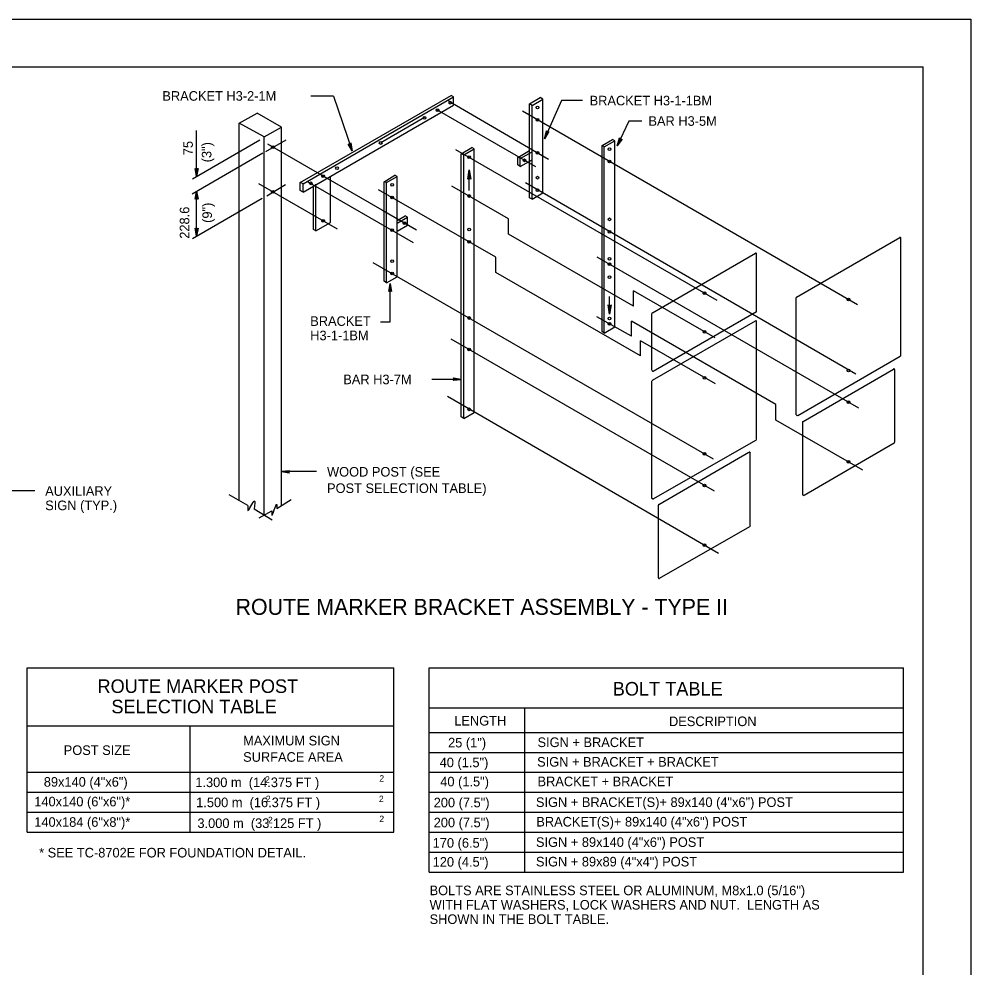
# Model space of a CAD drawing. Extents: x 649454 to 651200, y 295188 to 295782.
# Drawn here: x 650838.3 to 651136.3, y 295484.6 to 295781.6 of the extents above; entities that cross this region are included whole.
import ezdxf

# ---------------------------------------------------------------- set-up
doc = ezdxf.new("R2010")
doc.units = 0
for name, color, linetype in [('1', 7, 'Continuous'), ('2', 7, 'Continuous'), ('3', 7, 'Continuous'), ('PLT-BNDY', 7, 'Continuous')]:
    doc.layers.add(name, color=color, linetype=linetype)

msp = doc.modelspace()

# ---------------------------------------------------------------- linework, layer by layer
at = {"layer": '1'}
for p in [(650335.31, 295766.63), (651121.31, 295202.63)]:
    msp.add_line(p, (651121.31, 295766.63), dxfattribs=at)
at = {"layer": '2'}
for p, q in [((650840.87, 295578.52), (650955.61, 295578.52)), ((650840.87, 295527.15), (650840.87, 295578.52)), ((650955.61, 295527.15), (650955.61, 295578.52)), ((650966.73, 295578.52), (651115.19, 295578.52)), ((650966.73, 295514.65), (650966.73, 295578.52)), ((651115.19, 295514.65), (651115.19, 295578.52)), ((650966.73, 295566.02), (651115.19, 295566.02)), ((650996.61, 295514.65), (650996.61, 295565.9)), ((650840.87, 295560.46), (650955.61, 295560.46)), ((650891.86, 295527.02), (650891.86, 295560.34)), ((650966.73, 295558.27), (651115.19, 295558.27)), ((650966.73, 295552.02), (651115.19, 295552.02)), ((650840.87, 295545.9), (650955.61, 295545.9)), ((650966.73, 295545.9), (651115.19, 295545.9)), ((650840.87, 295539.65), (650955.61, 295539.65)), ((650966.73, 295539.65), (651115.19, 295539.65)), ((650840.87, 295533.4), (650955.61, 295533.4)), ((650966.73, 295533.4), (651115.19, 295533.4)), ((650840.87, 295527.15), (650955.61, 295527.15)), ((650966.73, 295527.15), (651115.19, 295527.15)), ((650966.73, 295520.9), (651115.19, 295520.9)), ((650966.73, 295514.65), (651115.19, 295514.65))]:
    msp.add_line(p, q, dxfattribs=at)
for points in [[(650936.7, 295757.45), (650929.62, 295757.45)], [(650936.7, 295757.45), (650942.56, 295740.33)], [(651008.11, 295756.11), (651002.79, 295744.14)], [(651014.71, 295756.11), (651008.11, 295756.11)], [(651033.31, 295749.71), (651029.19, 295749.71), (651025.56, 295741.96)], [(651004.04, 295746.27), (651003.79, 295746.27), (651002.79, 295744.14), (651004.04, 295746.27), (651004.16, 295746.39), (651002.79, 295744.14), (651003.54, 295746.39), (651003.54, 295746.52), (651002.79, 295744.14), (651003.41, 295746.64), (651003.54, 295746.52)], [(651026.94, 295743.96), (651026.69, 295743.96), (651025.56, 295741.96), (651026.94, 295743.96), (651027.06, 295744.08), (651025.56, 295741.96), (651026.44, 295744.08), (651026.31, 295744.21), (651025.56, 295741.96), (651026.31, 295744.46), (651026.31, 295744.21)], [(650942.06, 295742.58), (650941.94, 295742.46), (650942.56, 295740.33), (650942.06, 295742.58), (650942.19, 295742.83), (650942.56, 295740.33), (650941.69, 295742.46), (650941.56, 295742.46), (650942.56, 295740.33), (650941.31, 295742.46), (650941.56, 295742.46)], [(650951.44, 295686.83), (650954.44, 295686.83), (650954.44, 295698.83)], [(650954.19, 295696.46), (650954.31, 295696.58), (650954.44, 295698.83), (650954.19, 295696.46), (650954.06, 295696.33), (650954.44, 295698.83), (650954.56, 295696.58), (650954.81, 295696.46), (650954.44, 295698.83), (650954.94, 295696.33), (650954.81, 295696.46)], [(650976.69, 295668.83), (650967.56, 295668.83)], [(650974.31, 295669.21), (650974.44, 295668.96), (650976.69, 295668.83), (650974.31, 295669.21), (650974.19, 295669.21), (650976.69, 295668.83), (650974.44, 295668.71), (650974.31, 295668.58), (650976.69, 295668.83), (650974.19, 295668.46), (650974.31, 295668.58)], [(650922.81, 295639.58), (650922.69, 295639.83), (650920.44, 295639.96), (650922.81, 295639.58), (650922.94, 295639.46), (650920.44, 295639.96), (650922.69, 295640.08), (650922.81, 295640.21), (650920.44, 295639.96), (650922.94, 295640.33), (650922.81, 295640.21)], [(650931.38, 295639.96), (650920.44, 295639.96)], [(650843.26, 295633.97), (650833.19, 295633.97)]]:
    msp.add_lwpolyline(points, dxfattribs=at)
at = {"layer": '3'}
for p, q in [((650926.31, 295730.46), (650973.56, 295757.71)), ((650927.19, 295730.08), (650974.31, 295757.33)), ((651004.06, 295737.71), (650972.69, 295755.96)), ((650972.81, 295757.46), (650972.81, 295757.46)), ((650974.31, 295757.33), (650973.56, 295757.71)), ((650974.31, 295754.71), (650974.31, 295757.33)), ((650998.06, 295755.08), (651001.44, 295757.08)), ((650998.94, 295754.58), (651002.31, 295756.58)), ((651002.31, 295756.58), (651001.44, 295757.08)), ((651002.31, 295727.21), (651002.31, 295756.58)), ((650907.19, 295749.08), (650912.81, 295752.21)), ((650920.44, 295747.83), (650912.81, 295752.21)), ((650927.19, 295727.46), (650974.31, 295754.71)), ((651000.06, 295735.33), (650969.31, 295753.08)), ((650973.69, 295754.46), (650973.69, 295754.46)), ((651100.81, 295692.21), (650995.94, 295752.83)), ((650998.06, 295725.71), (650998.06, 295755.08)), ((650998.94, 295754.58), (650998.06, 295755.08)), ((650998.94, 295725.21), (650998.94, 295754.58)), ((650965.19, 295750.83), (650951.56, 295742.83)), ((650893.81, 295732.46), (650893.81, 295746.78)), ((650907.19, 295630.83), (650907.19, 295749.08)), ((650915.06, 295744.71), (650907.19, 295749.08)), ((650915.06, 295744.71), (650920.44, 295747.83)), ((650920.44, 295629.46), (650920.44, 295747.83)), ((650892.56, 295731.58), (650913.69, 295743.83)), ((650915.06, 295626.21), (650915.06, 295744.71)), ((650915.56, 295740.21), (650921.94, 295743.83)), ((651020.81, 295742.08), (651024.06, 295743.96)), ((651021.44, 295741.58), (651024.81, 295743.46)), ((651024.81, 295743.46), (651024.06, 295743.96)), ((651024.81, 295685.33), (651024.81, 295743.46)), ((650960.81, 295716.71), (650916.19, 295742.46)), ((650917.81, 295741.58), (650917.81, 295741.58)), ((651056.81, 295693.58), (650975.06, 295740.71)), ((650976.69, 295739.46), (650980.06, 295741.46)), ((650977.56, 295739.08), (650980.81, 295740.96)), ((650980.81, 295740.96), (650980.06, 295741.46)), ((650980.81, 295658.46), (650980.81, 295740.96)), ((650994.44, 295738.33), (650998.06, 295740.46)), ((651020.81, 295683.83), (651020.81, 295742.08)), ((651021.44, 295741.58), (651020.81, 295742.08)), ((651021.44, 295683.33), (651021.44, 295741.58)), ((650892.44, 295726.96), (650914.56, 295739.71)), ((650976.69, 295657.08), (650976.69, 295739.46)), ((650977.56, 295739.08), (650976.69, 295739.46)), ((650977.56, 295656.58), (650977.56, 295739.08)), ((650995.19, 295737.96), (650994.44, 295738.46)), ((650994.44, 295735.96), (650994.44, 295738.33)), ((650995.19, 295737.96), (650998.94, 295740.08)), ((650995.19, 295735.46), (650995.19, 295737.96)), ((650995.19, 295735.46), (650998.94, 295737.58)), ((650979.19, 295727.96), (650979.19, 295734.46)), ((650995.19, 295735.46), (650994.44, 295735.96)), ((650933.56, 295732.46), (650933.56, 295732.46)), ((650935.81, 295717.96), (650935.81, 295732.46)), ((650952.56, 295730.71), (650955.94, 295732.71)), ((650953.31, 295730.46), (650956.69, 295732.33)), ((650956.69, 295732.33), (650955.94, 295732.71)), ((650956.69, 295700.96), (650956.69, 295732.33)), ((650937.94, 295715.83), (650913.31, 295730.08)), ((650915.81, 295726.33), (650921.69, 295729.83)), ((650927.19, 295730.08), (650926.31, 295730.46)), ((650926.31, 295727.96), (650926.31, 295730.46)), ((650927.19, 295727.46), (650927.19, 295730.08)), ((650927.19, 295730.08), (650927.19, 295730.08)), ((650961.81, 295711.58), (650928.44, 295730.83)), ((650930.44, 295715.71), (650930.44, 295729.46)), ((650931.19, 295715.33), (650931.19, 295729.96)), ((650952.56, 295699.58), (650952.56, 295730.71)), ((650953.31, 295730.46), (650952.56, 295730.71)), ((650953.31, 295699.08), (650953.31, 295730.46)), ((650991.56, 295719.08), (650973.81, 295729.33)), ((651100.31, 295670.46), (650996.81, 295730.33)), ((650892.56, 295712.96), (650914.44, 295725.58)), ((650893.81, 295713.71), (650893.81, 295727.71)), ((650917.81, 295727.46), (650917.81, 295727.46)), ((650927.19, 295727.46), (650926.31, 295727.96)), ((650933.56, 295728.21), (650933.56, 295728.21)), ((650987.56, 295707.08), (650950.81, 295728.21)), ((650998.94, 295725.21), (650998.06, 295725.71)), ((650998.94, 295725.21), (651002.31, 295727.21)), ((651004.44, 295727.96), (651004.44, 295727.96)), ((650962.69, 295715.58), (650952.06, 295721.71)), ((650956.69, 295718.58), (650959.19, 295720.08)), ((650956.69, 295717.71), (650959.94, 295719.58)), ((650959.94, 295719.58), (650959.19, 295720.08)), ((650959.94, 295717.08), (650959.94, 295719.58)), ((650931.19, 295715.33), (650935.81, 295717.96)), ((650933.56, 295718.46), (650933.56, 295718.46)), ((650956.69, 295715.21), (650959.94, 295717.08)), ((650958.94, 295717.83), (650958.94, 295717.83)), ((650991.56, 295714.33), (650991.56, 295719.08)), ((650931.19, 295715.33), (650930.44, 295715.71)), ((650958.94, 295713.46), (650958.94, 295713.46)), ((651030.69, 295691.71), (650991.56, 295714.33)), ((651081.69, 295694.58), (651114.06, 295713.21)), ((651114.31, 295676.33), (651114.31, 295712.96)), ((651036.56, 295689.71), (651068.81, 295708.33)), ((651069.19, 295690.21), (651069.19, 295708.08)), ((651055.69, 295643.83), (650949.19, 295705.33)), ((650987.56, 295702.33), (650987.56, 295707.08)), ((651101.19, 295659.83), (651019.31, 295707.08)), ((651032.81, 295676.21), (650987.56, 295702.33)), ((650953.31, 295699.08), (650952.56, 295699.58)), ((650953.31, 295699.08), (650956.69, 295700.96)), ((651056.19, 295681.83), (651030.69, 295696.58)), ((651030.69, 295691.71), (651030.69, 295696.58)), ((651023.19, 295689.21), (651023.19, 295694.83)), ((651081.56, 295657.71), (651081.56, 295694.46)), ((651036.81, 295671.46), (651069.19, 295690.08)), ((651030.06, 295682.33), (651019.19, 295688.46)), ((651030.06, 295682.33), (651030.06, 295687.08)), ((651075.19, 295660.96), (651030.06, 295687.08)), ((651036.44, 295671.71), (651036.44, 295689.46)), ((651036.56, 295668.58), (651068.81, 295687.21)), ((651069.19, 295650.21), (651069.19, 295686.96)), ((651021.44, 295683.33), (651020.81, 295683.83)), ((651021.44, 295683.33), (651024.81, 295685.33)), ((651056.06, 295633.83), (650973.56, 295681.46)), ((651056.31, 295667.46), (651032.81, 295680.96)), ((651032.81, 295676.21), (651032.81, 295680.96)), ((651082.06, 295657.58), (651114.19, 295676.08)), ((651083.81, 295655.71), (651112.06, 295672.08)), ((651112.44, 295649.21), (651112.44, 295671.96)), ((651036.44, 295631.58), (651036.44, 295668.33)), ((651057.31, 295614.33), (650972.44, 295663.46)), ((651075.19, 295656.08), (651075.19, 295660.96)), ((650977.56, 295656.58), (650976.69, 295657.08)), ((650977.56, 295656.58), (650980.81, 295658.46)), ((651102.44, 295640.46), (651075.19, 295656.08)), ((651083.69, 295632.83), (651083.69, 295655.58)), ((651036.81, 295631.46), (651069.19, 295649.96)), ((651084.06, 295632.58), (651112.31, 295648.96)), ((651038.56, 295629.71), (651066.81, 295646.08)), ((651067.19, 295623.08), (651067.19, 295645.83)), ((650909.94, 295629.33), (650904.06, 295632.71)), ((650918.94, 295628.46), (650923.44, 295631.21)), ((650917.56, 295624.83), (650911.94, 295628.21)), ((650913.44, 295625.46), (650917.44, 295627.71)), ((651038.44, 295606.71), (651038.44, 295629.46)), ((651038.81, 295606.58), (651067.06, 295622.83))]:
    msp.add_line(p, q, dxfattribs=at)
for points in [[(650894.19, 295734.71), (650894.06, 295734.71), (650893.81, 295732.46), (650894.19, 295734.71), (650894.31, 295734.83), (650893.81, 295732.46), (650893.81, 295734.71), (650893.56, 295734.71), (650893.81, 295732.46), (650893.44, 295734.83), (650893.56, 295734.71)], [(650978.94, 295731.58), (650979.06, 295731.71), (650979.19, 295734.46), (650978.94, 295731.58), (650978.81, 295731.46), (650979.19, 295734.46), (650979.31, 295731.71), (650979.44, 295731.71), (650979.19, 295734.46), (650979.69, 295731.46), (650979.44, 295731.71)], [(650893.56, 295725.33), (650893.69, 295725.46), (650893.81, 295727.71), (650893.56, 295725.33), (650893.44, 295725.21), (650893.81, 295727.71), (650893.94, 295725.46), (650894.19, 295725.33), (650893.81, 295727.71), (650894.31, 295725.21), (650894.19, 295725.33)], [(650894.19, 295716.08), (650894.06, 295715.96), (650893.81, 295713.71), (650894.19, 295716.08), (650894.31, 295716.21), (650893.81, 295713.71), (650893.81, 295715.96), (650893.56, 295716.08), (650893.81, 295713.71), (650893.44, 295716.21), (650893.56, 295716.08)], [(651023.56, 295691.96), (651023.31, 295691.83), (651023.19, 295689.21), (651023.56, 295691.96), (651023.69, 295692.21), (651023.19, 295689.21), (651023.06, 295691.83), (651022.81, 295691.96), (651023.19, 295689.21), (651022.69, 295692.21), (651022.81, 295691.96)]]:
    msp.add_lwpolyline(points, dxfattribs=at)
for centre in [(650973.31, 295755.46), (650969.3, 295753.11), (651000.6, 295753.97), (650965.19, 295750.74), (651000.6, 295750.07), (650951.51, 295742.84), (650917.78, 295741.53), (651000.6, 295739.78), (651023.18, 295740.93), (650979.2, 295738.39), (650996.5, 295737.4), (651023.18, 295737.03), (650937.82, 295734.95), (650933.5, 295732.46), (651000.6, 295731.97), (650929.6, 295730.21), (650955.06, 295729.7), (651000.6, 295728.08), (650917.78, 295727.53), (650955.06, 295725.81), (650979.19, 295726.25), (651023.18, 295718.94), (650933.5, 295718.45), (650958.96, 295717.76), (650955.06, 295715.51), (650979.2, 295715.77), (651023.18, 295715.04), (650979.19, 295711.88), (650955.06, 295705.88), (651023.18, 295706.59), (651023.18, 295704.91), (650955.06, 295701.99), (651023.18, 295700.86), (651052.85, 295695.86), (651098, 295693.83), (650979.19, 295688.05), (651023.18, 295687.91), (651023.18, 295686.23), (651052.85, 295683.73), (650979.19, 295678.17), (651098, 295671.59), (651052.85, 295669.34), (650979.2, 295659.48), (651098, 295661.7), (651052.85, 295645.53), (651098, 295643.02), (651052.85, 295635.64), (651052.85, 295616.95)]:
    msp.add_circle(centre, 0.428, dxfattribs=at)
for centre, start, end in [((651114.1, 295713.04), 0, 119.9855), ((651068.95, 295708.1), 0, 119.9917), ((651081.9, 295694.46), 120.0061, 180), ((651036.75, 295689.52), 119.9995, 180), ((651068.95, 295690.25), 299.9933, 0), ((651068.95, 295686.98), 0, 119.999), ((651114.1, 295676.31), 299.9962, 0), ((651036.75, 295671.67), 180, 299.9946), ((651112.15, 295671.92), 0, 119.9857), ((651036.75, 295668.39), 120.001, 180), ((651081.9, 295657.73), 180, 299.9902), ((651083.85, 295655.58), 119.9982, 180), ((651068.95, 295650.25), 299.9789, 0), ((651112.15, 295649.14), 299.9948, 0), ((651067, 295645.85), 0, 119.9851), ((651036.75, 295631.66), 180, 299.9917), ((651083.85, 295632.8), 180, 299.9954), ((651038.7, 295629.52), 119.9949, 180), ((651067, 295623.07), 299.9719, 0), ((651038.7, 295606.74), 180, 299.9955)]:
    msp.add_arc(centre, 0.249, start, end, dxfattribs=at)
for points in [[(650909.94, 295629.33), (650909.94, 295627.83), (650911.94, 295630.83), (650911.94, 295628.21)], [(650917.44, 295627.71), (650917.44, 295626.21), (650918.94, 295629.71), (650918.94, 295628.46)]]:
    msp.add_spline(points, degree=3, dxfattribs=at)
at = {"layer": 'PLT-BNDY'}
msp.add_lwpolyline([(650295.31, 295781.63), (651136.31, 295781.63), (651136.31, 295187.63), (650295.31, 295187.63)], close=True, dxfattribs=at)

# ---------------------------------------------------------------- texts
at = {"layer": '2'}
for s, height, p in [('ROUTE MARKER BRACKET ASSEMBLY - TYPE II', 5, (650906.07, 295595.15)), ('LENGTH', 3, (650974.54, 295560.51)), ('DESCRIPTION', 3, (651041.77, 295560.32)), ('MAXIMUM SIGN', 3, (650908.44, 295554.28)), ('25 (1")', 3, (650972.6, 295553.65)), ('SIGN + BRACKET', 3, (651000.61, 295553.76)), ('POST SIZE', 3, (650852.27, 295551.29)), ('SURFACE AREA', 3, (650908.44, 295549.16)), ('40 (1.5")', 3, (650969.97, 295547.46)), ('SIGN + BRACKET + BRACKET', 3, (651000.48, 295547.64)), ('89x140 (4"x6")', 3, (650846.03, 295541.36)), ('1.300 m  (14.375 FT )', 3, (650893.47, 295541.23)), ('2', 2, (650915.31, 295542.61)), ('2', 2, (650951.09, 295542.97)), ('40 (1.5")', 3, (650970.16, 295541.46)), ('BRACKET + BRACKET', 3, (651000.61, 295541.51)), ('140x140 (6"x6")*', 3, (650843.05, 295535.2)), ('1.500 m  (16.375 FT )', 3, (650893.74, 295534.95)), ('2', 2, (650915.57, 295536.57)), ('2', 2, (650950.96, 295536.57)), ('200 (7.5")', 3, (650968.1, 295534.9)), ('SIGN + BRACKET(S)+ 89x140 (4"x6") POST', 3, (651000.11, 295535.02)), ('140x184 (6"x8")*', 3, (650843.05, 295528.8)), ('3.000 m  (33.125 FT )', 3, (650894.13, 295528.43)), ('2', 2, (650916.23, 295529.93)), ('2', 2, (650951.09, 295530.29)), ('200 (7.5")', 3, (650968.1, 295528.65)), ('BRACKET(S)+ 89x140 (4"x6") POST', 3, (651000.23, 295528.9)), ('SIGN + 89x140 (4"x6") POST', 3, (651000.11, 295522.52)), ('170 (6.5")', 3, (650967.78, 295522.27)), ('120 (4.5")', 3, (650967.78, 295516.33)), ('SIGN + 89x89 (4"x4") POST', 3, (651000.11, 295516.4)), ('BOLTS ARE STAINLESS STEEL OR ALUMINUM, M8x1.0 (5/16")', 3, (650966.82, 295507.4)), ('WITH FLAT WASHERS, LOCK WASHERS AND NUT.  LENGTH AS', 3, (650966.82, 295502.9)), ('SHOWN IN THE BOLT TABLE.', 3, (650966.82, 295498.4))]:
    msp.add_text(s, height=height, dxfattribs=at).set_placement(p)
at = {"layer": '3'}
for s, height, p in [('BRACKET H3-2-1M', 3, (650883.15, 295756.06)), ('BRACKET H3-1-1BM', 3, (651016.92, 295754.61)), ('BAR H3-5M', 3, (651035.33, 295748.21)), ('BRACKET', 3, (650929.45, 295685.59)), ('H3-1-1BM', 3, (650929.45, 295681.09)), ('BAR H3-7M', 3, (650939.79, 295667.33)), ('WOOD POST (SEE', 3, (650934.71, 295638.42)), ('POST SELECTION TABLE)', 3, (650934.71, 295633.29)), ('AUXILIARY', 3, (650846.47, 295632.41)), ('SIGN (TYP.)', 3, (650846.47, 295627.91)), ('ROUTE MARKER POST', 4.25, (650862.84, 295570.7)), ('BOLT TABLE', 4.25, (651024.16, 295569.88)), ('SELECTION TABLE', 4.25, (650867.19, 295564.33)), ('* SEE TC-8702E FOR FOUNDATION DETAIL.', 3, (650844.57, 295519.21))]:
    msp.add_text(s, height=height, dxfattribs=at).set_placement(p)
for s, p in [('75', (650892.69, 295739)), ('(3")', (650898.51, 295736.78)), ('228.6', (650891.59, 295712.86)), ('(9")', (650898.69, 295717.83))]:
    msp.add_text(s, height=3, rotation=90, dxfattribs=at).set_placement(p)

doc.saveas('drawing.dxf')
